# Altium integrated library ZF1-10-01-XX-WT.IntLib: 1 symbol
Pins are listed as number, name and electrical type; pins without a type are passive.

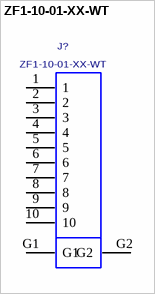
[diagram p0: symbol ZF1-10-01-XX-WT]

## ZF1-10-01-XX-WT
designator J?
ZERO INSERTION FORCE 1mm ASSEMBLY, BOTTOM CONTACT.; MANUFACTURER: SAMTEC
footprint ZF1-10-01-XX-WT
pins: 1, 2, 3, 4, 5, 6, 7, 8, 9, 10, G1, G2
